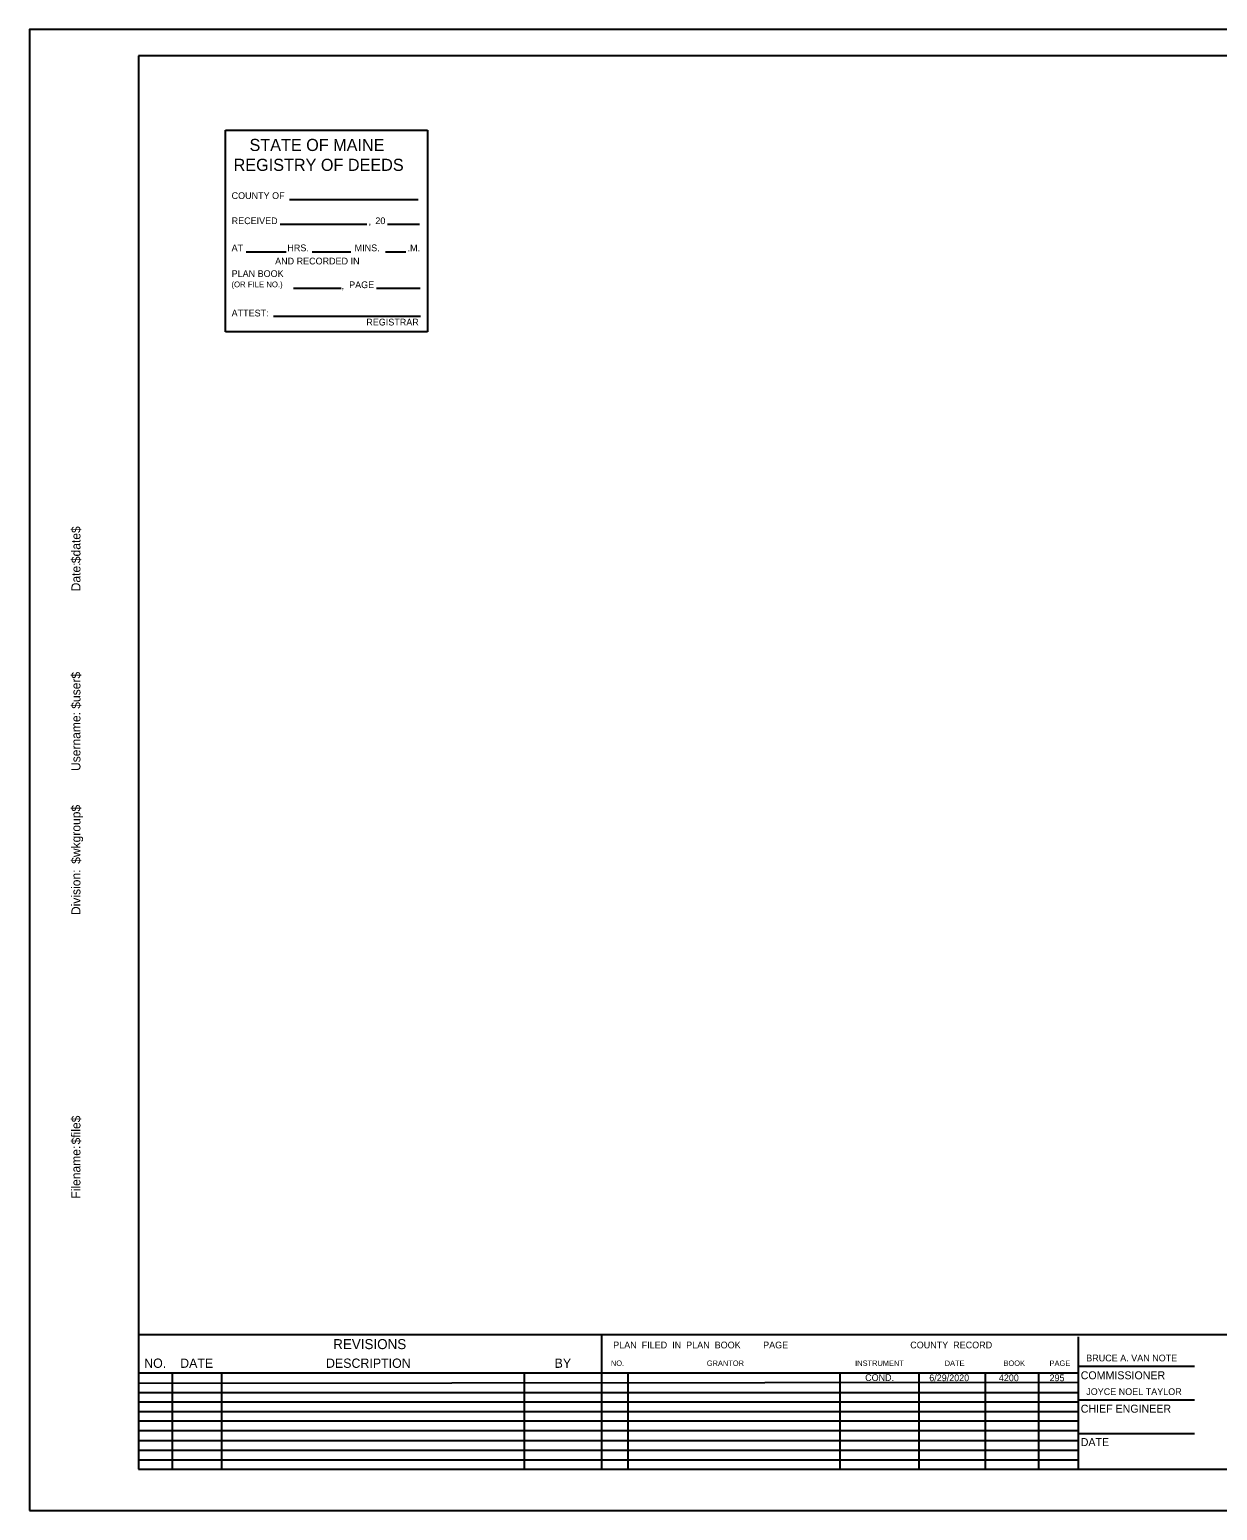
# Model space of a CAD drawing. Extents: x -415 to 435, y -303 to 247.
# Drawn here: x -415 to 26, y -303 to 247 of the extents above; entities that cross this region are included whole.
import ezdxf

# ---------------------------------------------------------------- set-up
doc = ezdxf.new("R2010")
doc.units = 0
for name, color, linetype in [('Border', 7, 'Continuous'), ('EX ROW NOTES', 7, 'Continuous'), ('PLOT BOUNDARY', 7, 'Continuous'), ('PRPTY SETUPS', 7, 'Continuous')]:
    doc.layers.add(name, color=color, linetype=linetype)

msp = doc.modelspace()

# ---------------------------------------------------------------- linework, layer by layer
at = {"layer": 'Border'}
for p, q in [((425, 237.5), (-375, 237.5)), ((-375, 237.5), (-375, -287.5)), ((-375, -237.49), (425, -237.49)), ((-202.99, -237.49), (-202.99, -287.5)), ((-25.83, -238.29), (-25.83, -287.5)), ((-375, -251.67), (-25.83, -251.67)), ((-362.5, -251.67), (-362.5, -287.5)), ((-344.13, -251.67), (-344.13, -287.5)), ((-231.63, -251.67), (-231.63, -287.5)), ((-193.15, -251.67), (-193.15, -287.5)), ((-114.41, -251.67), (-114.41, -287.5)), ((-84.88, -287.5), (-84.88, -251.67)), ((-60.27, -287.5), (-60.27, -251.67)), ((-40.59, -251.67), (-40.59, -287.5)), ((-25.83, -249.2), (17.41, -249.2)), ((-375, -255.6), (-25.83, -255.22)), ((-375, -258.96), (-25.83, -258.96)), ((-375, -262.5), (-26.02, -262.5)), ((-25.83, -261.7), (17.41, -261.7)), ((-375, -266.04), (-25.83, -266.04)), ((-375, -269.59), (-25.83, -269.59)), ((-375, -273.13), (-25.63, -273.13)), ((-25.83, -274.2), (17.41, -274.2)), ((-375, -276.87), (-25.83, -276.87)), ((-375, -280.41), (-25.83, -280.41)), ((-375, -283.96), (-25.83, -283.96)), ((-375, -287.5), (425, -287.5))]:
    msp.add_line(p, q, dxfattribs=at)
at = {"layer": 'PLOT BOUNDARY'}
msp.add_lwpolyline([(-415.47, -302.8), (434.53, -302.8), (434.53, 247.2), (-415.47, 247.2)], close=True, dxfattribs=at)
at = {"layer": 'PRPTY SETUPS'}
for p, q in [((-342.65, 209.9), (-267.67, 209.9)), ((-342.65, 134.92), (-342.65, 209.9)), ((-267.67, 209.9), (-267.67, 134.92)), ((-318.84, 184.14), (-271.1, 184.14)), ((-322.38, 174.97), (-290.15, 174.97)), ((-282.43, 174.97), (-270.57, 174.97)), ((-334.96, 164.69), (-320.17, 164.69)), ((-310.42, 164.69), (-296.06, 164.69)), ((-283.23, 164.69), (-275.68, 164.69)), ((-317.35, 151.18), (-299.64, 151.18)), ((-286.51, 151.18), (-270.33, 151.18)), ((-324.78, 140.73), (-270.24, 140.73)), ((-267.67, 134.92), (-342.65, 134.92))]:
    msp.add_line(p, q, dxfattribs=at)

# ---------------------------------------------------------------- texts
at = {"layer": 'Border'}
for s, height, rotation, p in [('$date$', 3.348, 90, (-396.58, 49.03)), ('Date:', 3.348, 90, (-396.58, 38.58)), ('$user$', 3.348, 90, (-396.58, -5.04)), ('Username:', 3.348, 90, (-396.58, -28.16)), ('$wkgroup$', 3.348, 90, (-396.58, -62.65)), ('Division:', 3.348, 90, (-396.58, -81.67)), ('$file$', 3.348, 90, (-396.58, -166.87)), ('Filename:', 3.348, 90, (-396.58, -187.01)), ('REVISIONS', 3.726, 360, (-302.65, -242.9)), ('NO.', 3.445, 360, (-372.89, -249.85)), ('DATE', 3.445, 360, (-359.52, -249.85)), ('DESCRIPTION', 3.4449, 360, (-305.33, -249.85)), ('BY', 3.445, 360, (-220.38, -249.85)), ('COMMISSIONER', 2.9528, 360, (-24.87, -254.1)), ('CHIEF ENGINEER', 2.9528, 360, (-24.87, -266.5)), ('DATE', 2.953, 360, (-24.87, -278.9))]:
    msp.add_text(s, height=height, rotation=rotation, dxfattribs=at).set_placement(p)
for s, height, p in [('PLAN  FILED  IN  PLAN  BOOK         PAGE', 2.4992, (-198.6, -242.62)), ('COUNTY  RECORD', 2.4992, (-88.23, -242.62)), ('NO.', 2, (-199.45, -249.13)), ('GRANTOR', 2, (-163.82, -249.13)), ('INSTRUMENT', 2, (-108.7, -249.13)), ('DATE', 2, (-75.43, -249.13)), ('BOOK', 2, (-53.58, -249.13)), ('PAGE', 2, (-36.46, -249.13)), ('BRUCE A. VAN NOTE', 2.5, (-22.83, -247.45)), ('JOYCE NOEL TAYLOR', 2.5, (-22.83, -259.95))]:
    msp.add_text(s, height=height, dxfattribs=at).set_placement(p)
at = {"layer": 'EX ROW NOTES'}
for s, p in [('COND.', (-104.97, -254.72)), ('6/29/2020', (-81.15, -254.8)), ('4200', (-55.29, -254.8)), ('295', (-36.46, -254.8))]:
    msp.add_text(s, height=2.49, dxfattribs=at).set_placement(p)
at = {"layer": 'PRPTY SETUPS'}
for s, height, p in [('STATE OF MAINE', 4.5, (-333.75, 202.12)), ('REGISTRY OF DEEDS', 4.5, (-339.66, 194.73)), ('COUNTY OF', 2.5, (-340.4, 184.29)), ('RECEIVED', 2.5, (-340.4, 174.95)), ('20', 2.5, (-286.99, 174.95)), (',', 2.61, (-289.53, 174.73)), ('AT', 2.5, (-340.4, 164.89)), ('HRS.', 2.5, (-319.68, 164.89)), ('MINS.', 2.5, (-294.67, 164.89)), ('.M.', 2.5, (-275.01, 164.89)), ('AND RECORDED IN', 2.5, (-324.24, 159.99)), ('PLAN BOOK ', 2.5, (-340.4, 155.32)), ('(OR FILE NO.)', 2.1531, (-340.46, 151.49)), (',', 2.61, (-299.59, 150.85)), ('PAGE', 2.5, (-296.73, 151.18)), ('ATTEST:', 2.5, (-340.4, 140.67)), ('REGISTRAR', 2.5, (-290.34, 137.31))]:
    msp.add_text(s, height=height, dxfattribs=at).set_placement(p)

doc.saveas('drawing.dxf')
